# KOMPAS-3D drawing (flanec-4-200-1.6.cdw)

Views: Вид 1
Referenced files: Фланец 5-150-1,6.cdw
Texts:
  Фланец 4-200-1,6 ГОСТ12820-80
  Инженер-конструктор
  Химстроймонтаж
  Технические требования по ГОСТ12816-80
  Ra 12,5
  Фланец 4-200-1,6
  ГОСТ12820-80
  Сталь О9Г2С-12 ГОСТ5520-79
Dimensions and other numbers on the sheet: 222; 239; 259; 295; 335; 4; 31; -12отв.; 22; 1:2; 1; 10,1; 0; 2; 3; 5; 6; 7; 8; 9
